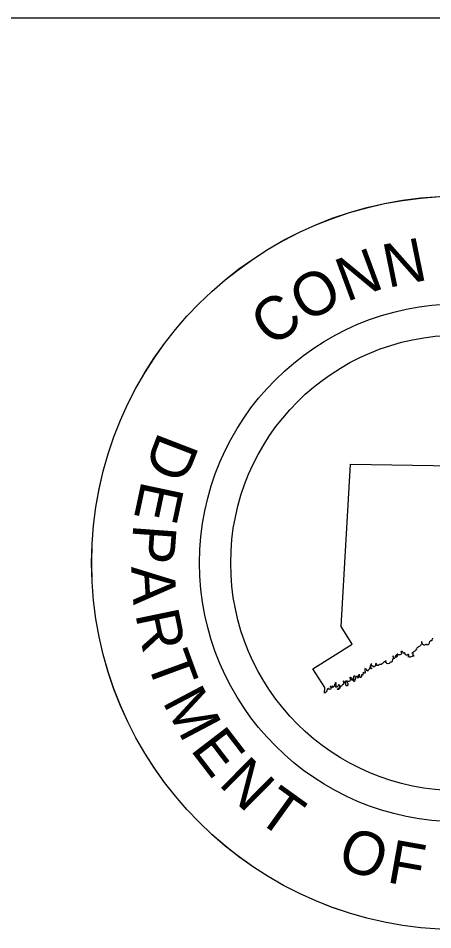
# Model space of a CAD drawing. Extents: x -0.14 to 2.7, y -0.05 to 1.78.
# Drawn here: x 1.3863 to 1.4182, y 0.01 to 0.08 of the extents above; entities that cross this region are included whole.
import ezdxf

# ---------------------------------------------------------------- set-up
doc = ezdxf.new("R2010")
doc.units = 0
doc.layers.add('BDR_Title_Block', color=7, linetype='Continuous')

msp = doc.modelspace()

# ---------------------------------------------------------------- linework, layer by layer
at = {"layer": 'BDR_Title_Block'}
for p, q in [((2.645833, 0.08), (0, 0.08)), ((1.411138, 0.033273), (1.411868, 0.045747)), ((1.411138, 0.033273), (1.411868, 0.045747)), ((1.411868, 0.045747), (1.420061, 0.045617)), ((1.411868, 0.045747), (1.420061, 0.045617)), ((1.411994, 0.031919), (1.411138, 0.033273)), ((1.411994, 0.031919), (1.411138, 0.033273)), ((1.408981, 0.030034), (1.411994, 0.031919)), ((1.408981, 0.030034), (1.411994, 0.031919)), ((1.409887, 0.02859), (1.408981, 0.030034)), ((1.409887, 0.02859), (1.408981, 0.030034))]:
    msp.add_line(p, q, dxfattribs=at)
msp.add_lwpolyline([(1.409874, 0.028166), (1.409887, 0.02859)], dxfattribs=at)
msp.add_lwpolyline([(1.409874, 0.028166), (1.409887, 0.02859)], dxfattribs=at)
for centre, major_axis in [((1.420154, 0.038164), (0, 0.028177)), ((1.420157, 0.038158), (0, 0.028177)), ((1.420154, 0.038164), (0, 0.01989)), ((1.420157, 0.038158), (0, 0.017498))]:
    msp.add_ellipse(centre, major_axis=major_axis, ratio=0.99999, dxfattribs=at)
for points in [[(1.41817, 0.03238), (1.418156, 0.03232), (1.418107, 0.032261), (1.418107, 0.032204), (1.418047, 0.032171), (1.41799, 0.032158), (1.417914, 0.032038), (1.417878, 0.031925), (1.417821, 0.031872), (1.417761, 0.031862), (1.417702, 0.031899), (1.417589, 0.031879), (1.417529, 0.031836), (1.417469, 0.031869), (1.417357, 0.032045), (1.417343, 0.032108), (1.41731, 0.032052), (1.417353, 0.031995), (1.417323, 0.031932), (1.41727, 0.031876), (1.417197, 0.031756), (1.417081, 0.03171), (1.417021, 0.03167), (1.416965, 0.03161), (1.416796, 0.031371), (1.416676, 0.031298)], [(1.41817, 0.03238), (1.418156, 0.03232), (1.418107, 0.032261), (1.418107, 0.032204), (1.418047, 0.032171), (1.41799, 0.032158), (1.417914, 0.032038), (1.417878, 0.031925), (1.417821, 0.031872), (1.417761, 0.031862), (1.417702, 0.031899), (1.417589, 0.031879), (1.417529, 0.031836), (1.417469, 0.031869), (1.417357, 0.032045), (1.417343, 0.032108), (1.41731, 0.032052), (1.417353, 0.031995), (1.417323, 0.031932), (1.41727, 0.031876), (1.417197, 0.031756), (1.417081, 0.03171), (1.417021, 0.03167), (1.416965, 0.03161), (1.416796, 0.031371), (1.416676, 0.031298)], [(1.416603, 0.031292), (1.416653, 0.031235), (1.416587, 0.031229), (1.416646, 0.031205), (1.416653, 0.031083), (1.416713, 0.031053), (1.416736, 0.030993), (1.41668, 0.030993), (1.416564, 0.03097), (1.416444, 0.03092), (1.416328, 0.030943), (1.416268, 0.030983), (1.416328, 0.030983), (1.416354, 0.031039), (1.416338, 0.031099), (1.416278, 0.031122), (1.416218, 0.031069), (1.416165, 0.031063), (1.416046, 0.031142), (1.416062, 0.031199), (1.416016, 0.031255), (1.41596, 0.031232), (1.4159, 0.031265), (1.415867, 0.031322), (1.4158, 0.031358), (1.415744, 0.031361), (1.415744, 0.031305), (1.41578, 0.031248), (1.415777, 0.031185), (1.415741, 0.031116), (1.415571, 0.031099), (1.415452, 0.031023), (1.415372, 0.030903), (1.415379, 0.03097), (1.415432, 0.031029), (1.415482, 0.031089), (1.415495, 0.031152), (1.415379, 0.031079), (1.415289, 0.030956), (1.415286, 0.0309), (1.415249, 0.03084), (1.41519, 0.030827), (1.415163, 0.030943), (1.41511, 0.031), (1.415143, 0.030943), (1.415147, 0.030887), (1.41514, 0.030827), (1.41507, 0.030648), (1.415064, 0.030585), (1.415004, 0.030548), (1.414944, 0.030532), (1.414831, 0.030432), (1.414655, 0.030442), (1.414606, 0.030502), (1.414543, 0.030528), (1.414543, 0.030591), (1.414602, 0.030641), (1.414546, 0.030625), (1.414489, 0.030565), (1.41443, 0.030535), (1.414327, 0.030426), (1.414267, 0.030406), (1.414211, 0.030356), (1.414095, 0.030346), (1.414035, 0.030326), (1.413978, 0.030283), (1.413915, 0.030306), (1.413859, 0.030286)], [(1.416603, 0.031292), (1.416653, 0.031235), (1.416587, 0.031229), (1.416646, 0.031205), (1.416653, 0.031083), (1.416713, 0.031053), (1.416736, 0.030993), (1.41668, 0.030993), (1.416564, 0.03097), (1.416444, 0.03092), (1.416328, 0.030943), (1.416268, 0.030983), (1.416328, 0.030983), (1.416354, 0.031039), (1.416338, 0.031099), (1.416278, 0.031122), (1.416218, 0.031069), (1.416165, 0.031063), (1.416046, 0.031142), (1.416062, 0.031199), (1.416016, 0.031255), (1.41596, 0.031232), (1.4159, 0.031265), (1.415867, 0.031322), (1.4158, 0.031358), (1.415744, 0.031361), (1.415744, 0.031305), (1.41578, 0.031248), (1.415777, 0.031185), (1.415741, 0.031116), (1.415571, 0.031099), (1.415452, 0.031023), (1.415372, 0.030903), (1.415379, 0.03097), (1.415432, 0.031029), (1.415482, 0.031089), (1.415495, 0.031152), (1.415379, 0.031079), (1.415289, 0.030956), (1.415286, 0.0309), (1.415249, 0.03084), (1.41519, 0.030827), (1.415163, 0.030943), (1.41511, 0.031), (1.415143, 0.030943), (1.415147, 0.030887), (1.41514, 0.030827), (1.41507, 0.030648), (1.415064, 0.030585), (1.415004, 0.030548), (1.414944, 0.030532), (1.414831, 0.030432), (1.414655, 0.030442), (1.414606, 0.030502), (1.414543, 0.030528), (1.414543, 0.030591), (1.414602, 0.030641), (1.414546, 0.030625), (1.414489, 0.030565), (1.41443, 0.030535), (1.414327, 0.030426), (1.414267, 0.030406), (1.414211, 0.030356), (1.414095, 0.030346), (1.414035, 0.030326), (1.413978, 0.030283), (1.413915, 0.030306), (1.413859, 0.030286)], [(1.413866, 0.030293), (1.413806, 0.030316), (1.413856, 0.030376), (1.413839, 0.030435), (1.413786, 0.030382), (1.413776, 0.030263), (1.413716, 0.030203), (1.413657, 0.030177), (1.413597, 0.03021), (1.413597, 0.030266), (1.41354, 0.030223), (1.413481, 0.030243), (1.413481, 0.030359), (1.413471, 0.030416), (1.413418, 0.030356), (1.413368, 0.030177), (1.413408, 0.030117), (1.413467, 0.030097), (1.413487, 0.030037), (1.413428, 0.030037), (1.413378, 0.030094), (1.413321, 0.030094), (1.413318, 0.030031), (1.413209, 0.029911), (1.413189, 0.029855), (1.413132, 0.029908), (1.413039, 0.030027), (1.412983, 0.030037), (1.41295, 0.029974), (1.41297, 0.029858), (1.412996, 0.029802), (1.412956, 0.029679), (1.412893, 0.029705), (1.412844, 0.029759), (1.412814, 0.029586), (1.412784, 0.029526), (1.412741, 0.029583), (1.412691, 0.02952), (1.412684, 0.02946), (1.412704, 0.0294), (1.412651, 0.02935), (1.412591, 0.029377), (1.412532, 0.029612), (1.412538, 0.029553), (1.412525, 0.029433), (1.412472, 0.02937), (1.412415, 0.029314), (1.412422, 0.02937), (1.412472, 0.02943), (1.412472, 0.029493), (1.412415, 0.02944), (1.412356, 0.02942), (1.412296, 0.029423), (1.412243, 0.029364), (1.412273, 0.029301), (1.41221, 0.029267), (1.412173, 0.029208), (1.41223, 0.029208), (1.412183, 0.029148), (1.412167, 0.029045)], [(1.413866, 0.030293), (1.413806, 0.030316), (1.413856, 0.030376), (1.413839, 0.030435), (1.413786, 0.030382), (1.413776, 0.030263), (1.413716, 0.030203), (1.413657, 0.030177), (1.413597, 0.03021), (1.413597, 0.030266), (1.41354, 0.030223), (1.413481, 0.030243), (1.413481, 0.030359), (1.413471, 0.030416), (1.413418, 0.030356), (1.413368, 0.030177), (1.413408, 0.030117), (1.413467, 0.030097), (1.413487, 0.030037), (1.413428, 0.030037), (1.413378, 0.030094), (1.413321, 0.030094), (1.413318, 0.030031), (1.413209, 0.029911), (1.413189, 0.029855), (1.413132, 0.029908), (1.413039, 0.030027), (1.412983, 0.030037), (1.41295, 0.029974), (1.41297, 0.029858), (1.412996, 0.029802), (1.412956, 0.029679), (1.412893, 0.029705), (1.412844, 0.029759), (1.412814, 0.029586), (1.412784, 0.029526), (1.412741, 0.029583), (1.412691, 0.02952), (1.412684, 0.02946), (1.412704, 0.0294), (1.412651, 0.02935), (1.412591, 0.029377), (1.412532, 0.029612), (1.412538, 0.029553), (1.412525, 0.029433), (1.412472, 0.02937), (1.412415, 0.029314), (1.412422, 0.02937), (1.412472, 0.02943), (1.412472, 0.029493), (1.412415, 0.02944), (1.412356, 0.02942), (1.412296, 0.029423), (1.412243, 0.029364), (1.412273, 0.029301), (1.41221, 0.029267), (1.412173, 0.029208), (1.41223, 0.029208), (1.412183, 0.029148), (1.412167, 0.029045)], [(1.412163, 0.029018), (1.412094, 0.029198), (1.41217, 0.0295), (1.412104, 0.029324), (1.41206, 0.029267), (1.412064, 0.029208), (1.412031, 0.029148), (1.412024, 0.029091), (1.411997, 0.029148), (1.411951, 0.029208), (1.411987, 0.029267), (1.411868, 0.029347), (1.411808, 0.029357), (1.411851, 0.029241), (1.411785, 0.029062), (1.411669, 0.029055), (1.411609, 0.029101), (1.411606, 0.029042), (1.411606, 0.028985), (1.411652, 0.028926), (1.411669, 0.028869), (1.411656, 0.028806), (1.411539, 0.028707), (1.411516, 0.028766), (1.41151, 0.028886), (1.41149, 0.028949), (1.411486, 0.029002), (1.411529, 0.029062), (1.411516, 0.029121), (1.411476, 0.029058), (1.41142, 0.029012), (1.41136, 0.029009), (1.41133, 0.029091)], [(1.412163, 0.029018), (1.412094, 0.029198), (1.41217, 0.0295), (1.412104, 0.029324), (1.41206, 0.029267), (1.412064, 0.029208), (1.412031, 0.029148), (1.412024, 0.029091), (1.411997, 0.029148), (1.411951, 0.029208), (1.411987, 0.029267), (1.411868, 0.029347), (1.411808, 0.029357), (1.411851, 0.029241), (1.411785, 0.029062), (1.411669, 0.029055), (1.411609, 0.029101), (1.411606, 0.029042), (1.411606, 0.028985), (1.411652, 0.028926), (1.411669, 0.028869), (1.411656, 0.028806), (1.411539, 0.028707), (1.411516, 0.028766), (1.41151, 0.028886), (1.41149, 0.028949), (1.411486, 0.029002), (1.411529, 0.029062), (1.411516, 0.029121), (1.411476, 0.029058), (1.41142, 0.029012), (1.41136, 0.029009), (1.41133, 0.029091)], [(1.41133, 0.029108), (1.41131, 0.029048), (1.41135, 0.028932), (1.411337, 0.028872), (1.4113, 0.028813), (1.411241, 0.028823), (1.411188, 0.028707), (1.411125, 0.028693), (1.411038, 0.02857), (1.411025, 0.028507), (1.410969, 0.028451), (1.410912, 0.028431), (1.410859, 0.028431), (1.410856, 0.028488), (1.410916, 0.028494), (1.410975, 0.028544), (1.411015, 0.0286), (1.411035, 0.02866), (1.411032, 0.02878), (1.410979, 0.028773), (1.410952, 0.028829), (1.410959, 0.028773), (1.410899, 0.02872), (1.410859, 0.02866), (1.410743, 0.02861), (1.41071, 0.028667), (1.410763, 0.028726), (1.41073, 0.028843), (1.410756, 0.028962), (1.4107, 0.028942), (1.41068, 0.028879), (1.410633, 0.028819), (1.410637, 0.02876), (1.410557, 0.028634), (1.410501, 0.028597), (1.410487, 0.028713), (1.410441, 0.028653), (1.410438, 0.028594), (1.410378, 0.028604), (1.410358, 0.02866), (1.410302, 0.02867), (1.410325, 0.028614), (1.410371, 0.028557), (1.410355, 0.028497), (1.410312, 0.028434), (1.410252, 0.028468), (1.410192, 0.028454), (1.410162, 0.028514), (1.410106, 0.028481), (1.410043, 0.028361), (1.41003, 0.028298), (1.409874, 0.028166)], [(1.41133, 0.029108), (1.41131, 0.029048), (1.41135, 0.028932), (1.411337, 0.028872), (1.4113, 0.028813), (1.411241, 0.028823), (1.411188, 0.028707), (1.411125, 0.028693), (1.411038, 0.02857), (1.411025, 0.028507), (1.410969, 0.028451), (1.410912, 0.028431), (1.410859, 0.028431), (1.410856, 0.028488), (1.410916, 0.028494), (1.410975, 0.028544), (1.411015, 0.0286), (1.411035, 0.02866), (1.411032, 0.02878), (1.410979, 0.028773), (1.410952, 0.028829), (1.410959, 0.028773), (1.410899, 0.02872), (1.410859, 0.02866), (1.410743, 0.02861), (1.41071, 0.028667), (1.410763, 0.028726), (1.41073, 0.028843), (1.410756, 0.028962), (1.4107, 0.028942), (1.41068, 0.028879), (1.410633, 0.028819), (1.410637, 0.02876), (1.410557, 0.028634), (1.410501, 0.028597), (1.410487, 0.028713), (1.410441, 0.028653), (1.410438, 0.028594), (1.410378, 0.028604), (1.410358, 0.02866), (1.410302, 0.02867), (1.410325, 0.028614), (1.410371, 0.028557), (1.410355, 0.028497), (1.410312, 0.028434), (1.410252, 0.028468), (1.410192, 0.028454), (1.410162, 0.028514), (1.410106, 0.028481), (1.410043, 0.028361), (1.41003, 0.028298), (1.409874, 0.028166)]]:
    msp.add_spline(points, degree=3, dxfattribs=at)

# ---------------------------------------------------------------- texts
for s, rotation, p in [('N', 11.47577, (1.414734, 0.059279)), ('N', 20.34787, (1.411541, 0.058191)), ('O', 29.5691, (1.408441, 0.056551)), ('C', 37.99655, (1.40587, 0.054636)), ('D', 248.92492, (1.397149, 0.048318)), ('E', 257.99776, (1.395835, 0.044564)), ('P', 265.8361, (1.39519, 0.041187)), ('A', 273.41275, (1.395009, 0.037869)), ('R', 281.70935, (1.395315, 0.034244)), ('T', 290.11028, (1.396154, 0.030657)), ('M', 297.80492, (1.397375, 0.027511)), ('E', 307.52378, (1.3995, 0.023819)), ('N', 315.36207, (1.40165, 0.021136)), ('T', 324.23418, (1.404497, 0.018486)), ('O', 340.69587, (1.410715, 0.014856)), ('F', 349.91723, (1.414573, 0.013644))]:
    msp.add_text(s, height=0.003333, rotation=rotation, dxfattribs=at).set_placement(p)

doc.saveas('drawing.dxf')
